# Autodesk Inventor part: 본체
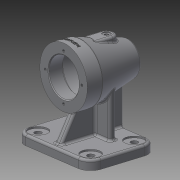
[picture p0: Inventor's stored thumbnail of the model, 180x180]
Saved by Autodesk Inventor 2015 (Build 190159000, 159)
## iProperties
Created: 2024-12
Part Number: 본체
Material: 일반
Document SubType Name: Modeling
Designer: 102566
Density: 1 g/cm^3
Appearance: 기본값
Author: 102566
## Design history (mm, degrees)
sketch "스케치1"
  geometry: L1 (57, 44.5)-(-57, 44.5); L2 (-57, 44.5)-(-57, -44.5); L3 (-57, -44.5)-(57, -44.5); L4 (57, -44.5)-(57, 44.5); L5 (57, 44.5)-(-57, -44.5); L6 (-57, 44.5)-(57, -44.5); 1 further point
  constraints: 12 end point, 2 midpoint, 2 parallel, 1 horizontal, 1 perpendicular
  dimensions: "d0" = 114 distance of L2.end L3.end; "d1" = 89 distance of L3.end L1.start
extrude "돌출1" new body sketch "스케치1" distance "d2" = 12; taper "d3" = 0 deg
sketch "스케치3"
  geometry: L1 (82, 35.374)-(82, -61.09); L2 (82, 29.5)-(119, 29.5); L3 (119, 29.5)-(119, 9.5); L4 (0, 44.5)-(0, -44.5) reference; L5 (0, 44.5)-(12, 44.5) reference; L6 (119, 9.5)-(103, -54.5); L7 (103, -54.5)-(82, -54.5); 1 further point
  constraints: 10 end point, 2 perpendicular, 2 point on line, 1 horizontal, 1 vertical
  dimensions: "d7" = 119 distance between parallel lines of L4 L3; "d8" = 15 distance between parallel lines of L5 L2; "d11" = 20 distance of L2.end L3.end; "d12" = 84 distance between parallel lines of L7 L2; "d13" = 74 diameter of L3 L1; "d15" = 21 distance of L6.end L7.end
revolve "회전1" sketch "스케치3" stored, may be unused: angle "d16" = 90 deg
sketch "스케치4"
  geometry: L1 (57, 44.5)-(-57, 44.5) reference; L2 (-28, 15.5)-(28, 15.5); L3 (28, 15.5)-(28, 7.5); L4 (28, 7.5)-(-28, 7.5); L5 (-28, 7.5)-(-28, 15.5); 1 further point
  constraints: 8 end point, 2 parallel, 1 horizontal, 1 perpendicular
  dimensions: "d17" = 29 distance between parallel lines of L1 L2; "d18" = 8 distance of L4.end L2.start; "d19" = 56 distance of L2.start L2.end; "d20" = 28 distance from line of point (0, 0) L3
extrude "돌출2" join sketch "스케치4" stored distance "d21" = 18; taper "d22" = 0 deg
sketch "스케치5"
  geometry: L1 (57, 44.5)-(-57, 44.5) reference; L2 (-5, 44.5)-(5, 44.5); L3 (5, 44.5)-(5, 11.5); L4 (5, 11.5)-(-5, 11.5); L5 (-5, 11.5)-(-5, 44.5); 1 further point
  constraints: 8 end point, 2 parallel, 1 horizontal, 1 perpendicular, 1 point on line
  dimensions: "d23" = 10 distance of L3.end L4.end; "d24" = 5 distance from line of point (0, 0) L3; "d25" = 33 distance of L2.end L3.end
extrude "돌출3" join sketch "스케치5" stored distance "d26" = 18; taper "d27" = 0 deg
node "작업 평면2"
sketch "스케치6"
  geometry: L1 (7, 12)-(33.995, 58.757); L2 (33.995, 58.757)-(62.56, 58.757); L3 (62.56, 58.757)-(62.56, 12); L4 (7, 12)-(62.56, 12); L5 (89, 12)-(0, 12) reference; L6 (0, 0)-(0, 12) reference; L7 (89, 0)-(0, 0) reference; 1 further point
  constraints: 8 end point, 1 collinear, 1 horizontal, 1 perpendicular
  dimensions: "d29" = 7 distance from line of L6 L1.start; "d30" = 60 deg angle of L4 L1; "d31" = 28.56483 distance of L1.end L2.end; "d32" = 46.75708 distance of L2.end L3.end; "d33" = 12 distance between parallel lines of L7 L4
extrude "돌출4" join sketch "스케치6" stored distance "d34" = 10; taper "d35" = 0 deg
sketch "스케치7"
  geometry: L1 (15, 82)-(99, 82); L2 (15, 82)-(15, 105.5); L3 (33, 105.5)-(33, 107.489); L4 (39.29, 112.32)-(78, 101.981); L5 (78, 101.981)-(78, 99.5); L6 (78, 99.5)-(88, 99.5); L7 (88, 99.5)-(88, 97.5); L8 (88, 97.5)-(91, 97.5); L9 (91, 97.5)-(91, 82); L10 (33, 105.5)-(15, 105.5); L11 (89, 0)-(0, 0) reference; L12 (99, 61)-(99, 103) reference; A1 r 5 centre (38, 107.489) between (39.29, 112.32) and (33, 107.489); 2 further points
  constraints: 20 end point, 5 perpendicular, 3 point on line, 2 point on circle, 2 tangent, 1 centre point, 1 parallel, 1 vertical
  dimensions: "d36" = 47 diameter of L10 L1; "d37" = 45 distance between parallel lines of L5 L3; "d38" = 18 distance of L3.start L2.end; "d39" = 10 distance of L5.end L6.end; "d40" = 3 distance of L7.end L8.end; "d41" = 35 diameter of L6 L1; "d42" = 31 diameter of L8 L1; "d43" = 64 diameter of point (33, 114) L1; "d45" = 82 distance between parallel lines of L11 L1; "d99" = 5 radius of A1; "d100" = 90 deg angle of L10 L2; "d101" = 8 distance between parallel lines of L12 L9; "d102" = 104.954 deg angle of L5 L4
revolve "회전2" sketch "스케치7" stored, may be unused: angle "d46" = 90 deg
sketch "스케치8"
  geometry: L1 (-57, 44.5)-(-57, -44.5) reference; L2 (-57, -44.5)-(57, -44.5) reference; 2 further points
  dimensions: "d47" = 16 distance from line of L2 point (-41, -28.5); "d48" = 16 distance from line of L1 point (-41, -28.5)
hole "구멍1" sketch "스케치8" at (-41, -28.5) diameter "d49" = 9; stored, may be unused: countersink angle "d53" = 90 deg, drill point angle "d55" = 0 deg; dims "d50" = 6, "d51" = 24, "d52" = 2, "d54" = 8
sketch "스케치9" dims "d62" = 57
  geometry: C1 r 23.5 at (0, 0) reference; C2 r 37 at (0, 0) reference; 3 further points
  constraints: 2 vertical alignment, 1 coincident, 2 other
hole "구멍2" sketch "스케치9" at (0, 28.5) diameter "d63" = 3.242; stored, may be unused: countersink angle "d67" = 90 deg, drill point angle "d69" = 118 deg; dims "d64" = 8, "d65" = 24, "d66" = 2, "d68" = 11.8
node "작업 평면3"
sketch "스케치10"
  geometry: L1 (-10, 3.5)-(10, 3.5); L2 (10, 3.5)-(10, -36.5); L3 (10, -36.5)-(-10, -36.5); L4 (-10, -36.5)-(-10, 3.5); L5 (-37, 29.5)-(37, 29.5) reference; 1 further point
  constraints: 8 end point, 2 parallel, 1 horizontal, 1 perpendicular
  dimensions: "d74" = 20 distance of L2.end L3.end; "d75" = 66 distance between parallel lines of L5 L3; "d76" = 10 distance from line of point (0, 0) L2; "d77" = 40 distance of L1.end L2.end
extrude "돌출5" join sketch "스케치10" stored distance "d78" = 10; taper "d79" = 0 deg
fillet "모깎기1" dims "d80" = 16
fillet "모깎기2" dims "d81" = 3
fillet "모깎기3" dims "d82" = 3
fillet "모깎기4" dims "d83" = 3
sketch "스케치11"
  geometry: L1 (37, -29.5)-(-37, -29.5) reference; 2 further points
  dimensions: "d84" = 56 distance from line of L1 point (0, 26.5)
hole "구멍3" sketch "스케치11" at (0, 26.5) diameter "d85" = 4.917; stored, may be unused: countersink angle "d89" = 90 deg, drill point angle "d91" = 118 deg; dims "d86" = 12, "d87" = 10, "d88" = 1, "d90" = 17.55
fillet "모깎기5" dims "d92" = 10
fillet "모깎기6" dims "d93" = 3
node "작업 평면5"
sketch "스케치13"
  geometry: 3 further points
  constraints: 1 vertical alignment, 1 other
feature "엠보싱1" sketch "스케치13" dims "d0" = 114, "d1" = 89, "d96" = 0.5, "d97" = 0
fillet "모깎기7" dims "d98" = 0.3
fillet "모깎기8" dims "d103" = 3
chamfer "모따기1" distance "d104" = 1; stored, may be unused: second distance "d105" = 2, angle "d106" = 45 deg
fillet "모깎기9" dims "d107" = 3
fillet "모깎기10" dims "d108" = 3
fillet "모깎기11" dims "d109" = 3
node "솔리드1"
pattern_linear "직사각형 패턴1" dims "d58" = 57, "d61" = 82
pattern_circular "원형 패턴1" dims angle "d71" = 360 deg
other parameters: "d28" = -57, "d73" = -115
